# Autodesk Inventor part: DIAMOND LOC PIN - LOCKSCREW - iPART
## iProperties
Shininess: 20.0
Length Units: 11272
Angle Units: 11279
Time Units: 11290
Mass Units: 11286
Length Display Precision: 3
Angle Display Precision: 2
Created: 2002-08
Part Number: DIAMOND LOC PIN - LOCKSCREW - iPART
Material: Steel, High Strength Low Alloy
Document SubType Name: Modeling
Designer: Dan Trombley
Density: 0.0
Volumn: 0.0
Area: 0.0
PropertySet Name: Model Information
Control State: 0
Master: False
Checked Out: False
PSM: P
MATERIAL: 1018 CRS
BOM DESCRIPTION: CARR LANE LOCATION PIN
STK. SIZE (WELDMENT): -
BOM PART NUMBER: -
Title: ROUND & DIAMOND LOCATING PINS
Author: TROMBLD
Comments: iPart created based on dimensions given on pages 90 & 91 of Carr Lane Catalog. It contains Metric & English - Round Press Fit & Lockscrew Type and Diamond Press and Lockscrew Type.
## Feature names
1. Revolution1
2. Chamfer1
3. Extrusion4
4. Extrusion6
5. Chamfer3
6. Chamfer4
7. Extrusion7
